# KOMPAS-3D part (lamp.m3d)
File: created 18.09.2016 11:39:13, last saved 18.09.2016 11:49:18.
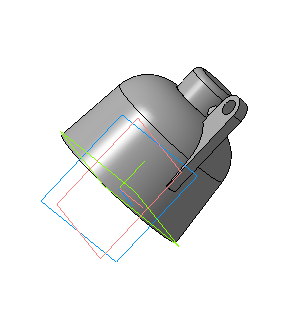
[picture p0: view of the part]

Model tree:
1. Эскиз:1
2. Операция вращения:1
     Угол 1 = 360
3. Эскиз:2
4. Операция выдавливания:1
     Расстояние 1 = 5
5. Эскиз:3
6. Вырезать элемент выдавливания:1
     Расстояние 2 = 15; Расстояние 1 = 10
7. Скругление:2
     Радиус = 3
